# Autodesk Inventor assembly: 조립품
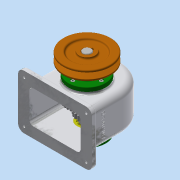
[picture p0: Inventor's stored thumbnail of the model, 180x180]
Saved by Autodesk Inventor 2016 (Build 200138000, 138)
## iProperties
Created: 2018-11
Part Number: 조립품
Material: 일반
Document SubType Name: Assembly
Designer: user
Author: user
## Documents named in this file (14)
- C:\Users\user\Desktop\481111V1002\조립품.iam
- C:\Users\user\Desktop\481111V1002\V-벨트풀리.ipt
- C:\Users\user\Desktop\481111V1002\뒤커버.ipt
- C:\Users\user\Desktop\481111V1002\멈춤나사 M4.ipt
- C:\Users\user\Desktop\481111V1002\베어링 6203.ipt
- C:\Users\user\Desktop\481111V1002\본체.ipt
- C:\Users\user\Desktop\481111V1002\볼트 M4.ipt
- C:\Users\user\Desktop\481111V1002\부시.ipt
- C:\Users\user\Desktop\481111V1002\스퍼기어.ipt
- C:\Users\user\Desktop\481111V1002\앞커버.ipt
- C:\Users\user\Desktop\481111V1002\오일 실 28 40 8.ipt
- C:\Users\user\Desktop\481111V1002\축.ipt
- C:\Users\user\Desktop\481111V1002\키 5x5x18.ipt
- C:\Users\user\Desktop\481111V1002\키 6x6x22.ipt
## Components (1 placed, 1 different names)
1. V-벨트풀리:1
